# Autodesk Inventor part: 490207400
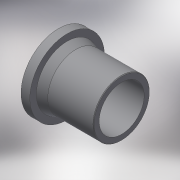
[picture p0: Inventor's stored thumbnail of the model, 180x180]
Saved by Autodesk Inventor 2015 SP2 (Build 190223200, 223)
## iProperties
Created: 2017-07
Part Number: 490207400
Material: Generic
Description: Stub Flange 400
Document SubType Name: Modeling
Designer: Кирилл
Mass: 15765.2 g
Surface Area: 8761.18 cm^2
Volume: 15765.2 cm^3
Density: 1 g/cm^3
Appearance: Default
Author: Кирилл
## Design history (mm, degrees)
derived "490207.ipt"
feature "Solid1::490207.ipt"
tag "TaggingFeature1"
body "Solid1"
other parameters: "d0" = 286, "d1" = 427, "d4" = 482, "d5" = 45, "d6" = 195, "d17" = 8, "d18" = 8, "d19" = 8, "d21" = 8, "d24" = 8, "d25" = 8, "d26" = 4, "d27" = 0, "d32" = 4, "L_" = 286, "L_1" = 195, "D_" = 482, "D_1" = 427, "a_" = 45
